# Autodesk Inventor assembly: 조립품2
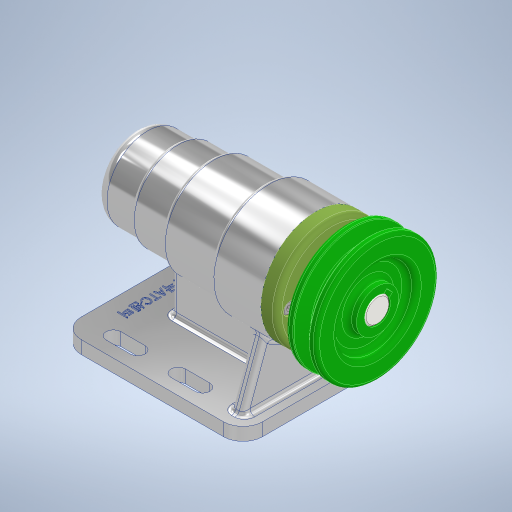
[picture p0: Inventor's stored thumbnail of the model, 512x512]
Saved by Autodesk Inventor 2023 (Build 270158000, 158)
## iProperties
Created: 2022-07
Part Number: 조립품2
Document SubType Name: Assembly
Designer: owner
Author: owner
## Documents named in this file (12)
- C:\Users\owner\Desktop\720708V1004\조립품2.iam
- C:\Users\owner\Desktop\720708V1004\본체.ipt
- C:\Users\owner\Desktop\720708V1004\V벨트풀리.ipt
- C:\Users\owner\Desktop\720708V1004\멈춤나사 M3.ipt
- C:\Users\owner\Desktop\720708V1004\베어링 6004.ipt
- C:\Users\owner\Desktop\720708V1004\베어링 51202.ipt
- C:\Users\owner\Desktop\720708V1004\볼트 M4.ipt
- C:\Users\owner\Desktop\720708V1004\어댑터슬리브.ipt
- C:\Users\owner\Desktop\720708V1004\오일 실 20x35x7.ipt
- C:\Users\owner\Desktop\720708V1004\축.ipt
- C:\Users\owner\Desktop\720708V1004\커버.ipt
- C:\Users\owner\Desktop\720708V1004\키 5x5.ipt
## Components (1 placed, 1 different names)
1. V벨트풀리:1 — 강체:7
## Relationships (1: WeldJoint 1)
- 강체:7 [WeldJoint]: V벨트풀리:1
